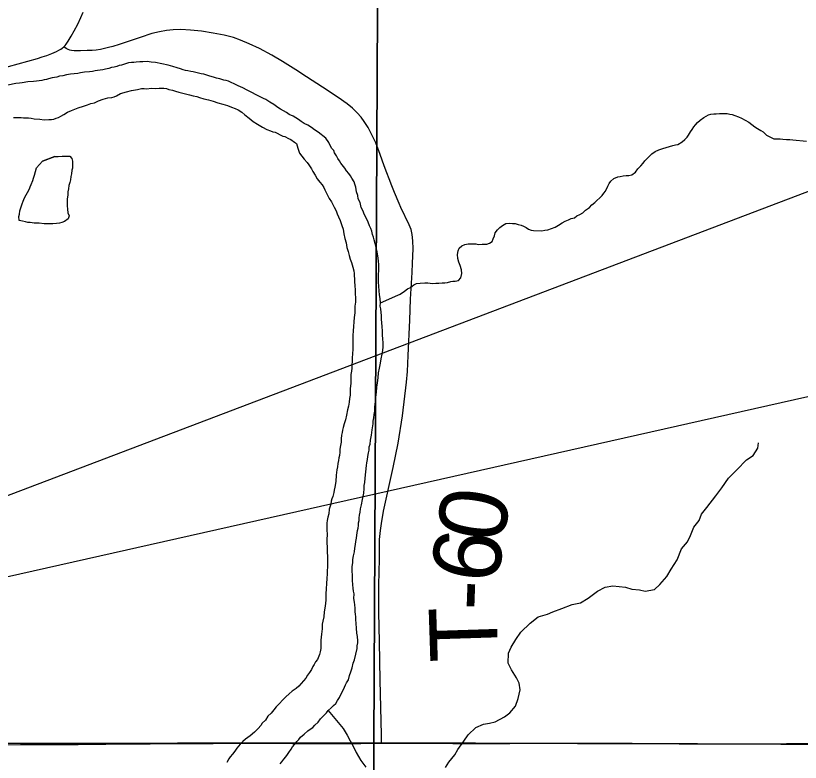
# Model space of a CAD drawing. Extents: x -17 to 88, y -5 to 22.
# Drawn here: x 6.404 to 7.061, y 17.134 to 17.759 of the extents above; entities that cross this region are included whole.
import ezdxf

# ---------------------------------------------------------------- set-up
doc = ezdxf.new("R2010")
doc.units = 0
for name, color, linetype in [('GM_X_County_Road', 7, 'Continuous'), ('GM_X_Major_River', 7, 'Continuous'), ('GM_X_Minor_Lake', 7, 'Continuous'), ('GM_X_Minor_River', 7, 'Continuous'), ('GM_X_Section', 7, 'Continuous'), ('GM_X_Township_Road', 7, 'Continuous'), ('GM_X_Township_Road_Text', 7, 'Continuous'), ('TX_P_10', 7, 'Continuous')]:
    doc.layers.add(name, color=color, linetype=linetype)

msp = doc.modelspace()

# ---------------------------------------------------------------- linework, layer by layer
at = {"layer": 'GM_X_County_Road'}
for points in [[(6.37699, 17.711), (6.38326, 17.71252), (6.39765, 17.71636), (6.42211, 17.72329), (6.4258, 17.72447), (6.42973, 17.72573), (6.4339, 17.72739), (6.43791, 17.72915), (6.43979, 17.73005), (6.4415, 17.73092), (6.44279, 17.73178), (6.44414, 17.73289)], [(5.97069, 17.14636), (6.02752, 17.14692), (6.1512, 17.14741), (6.20466, 17.14779), (6.24754, 17.14782), (6.31026, 17.14802), (6.39721, 17.14843), (6.40776, 17.14847), (6.42947, 17.14848), (6.45617, 17.14867), (6.50275, 17.14905), (6.51643, 17.1492), (6.56916, 17.14951), (6.60646, 17.14958), (6.63568, 17.14941), (6.69283, 17.14953), (6.70713, 17.14958), (6.71015, 17.14959)], [(6.71015, 17.14959), (6.76986, 17.14955), (6.81769, 17.14952), (6.85681, 17.14966), (6.89719, 17.14962), (6.92016, 17.14969), (6.97483, 17.14948), (7.01768, 17.14922), (7.04938, 17.14939), (7.11773, 17.14928), (7.13759, 17.14915), (7.21899, 17.14912)]]:
    msp.add_lwpolyline(points, dxfattribs=at)
at = {"layer": 'GM_X_Major_River'}
for points in [[(6.66717, 17.65023), (6.66608, 17.65291), (6.66348, 17.65638), (6.65711, 17.66143), (6.65411, 17.66339), (6.65148, 17.66534), (6.64848, 17.66729), (6.64547, 17.66887), (6.64283, 17.67043), (6.64058, 17.67199), (6.63833, 17.67355), (6.63607, 17.67474), (6.63268, 17.67632), (6.63043, 17.67788), (6.62817, 17.67944), (6.62553, 17.68063), (6.62328, 17.68219), (6.61991, 17.68453), (6.61652, 17.68649), (6.61314, 17.68883), (6.61126, 17.68963), (6.60862, 17.6912), (6.60523, 17.69278), (6.60147, 17.69474), (6.5977, 17.69671), (6.59394, 17.69868), (6.59017, 17.70027), (6.58677, 17.70185), (6.58413, 17.70304), (6.58187, 17.70422), (6.57998, 17.70464), (6.57809, 17.70505), (6.57469, 17.70626), (6.57203, 17.70669), (6.56939, 17.70749), (6.56636, 17.70831), (6.56372, 17.70912), (6.56145, 17.70992), (6.55918, 17.71034), (6.5569, 17.71076), (6.55464, 17.71157), (6.55236, 17.71199), (6.55047, 17.7124), (6.54782, 17.71283), (6.54592, 17.71325), (6.54403, 17.71366), (6.54177, 17.71446), (6.53912, 17.71527), (6.53534, 17.71648), (6.53156, 17.71769), (6.52096, 17.71979), (6.51716, 17.72024), (6.51375, 17.72068), (6.51032, 17.72036), (6.50766, 17.72042), (6.50461, 17.72009), (6.50271, 17.71975), (6.50081, 17.71978), (6.49814, 17.71945), (6.49584, 17.71874), (6.4924, 17.71766), (6.49049, 17.71732), (6.48858, 17.71659), (6.48628, 17.71588), (6.484, 17.71554), (6.4817, 17.71482), (6.47903, 17.71411), (6.47674, 17.71377), (6.47445, 17.71344), (6.47217, 17.7131), (6.47026, 17.71275), (6.46797, 17.71242), (6.46568, 17.71208), (6.4615, 17.71178), (6.45806, 17.71108), (6.45577, 17.71075), (6.45273, 17.71042), (6.44968, 17.7101), (6.44624, 17.7094), (6.44319, 17.7087), (6.44052, 17.70837), (6.43823, 17.70766), (6.43632, 17.70731), (6.43441, 17.70697), (6.43136, 17.70626), (6.42945, 17.70554), (6.42754, 17.7052), (6.42563, 17.70485), (6.42106, 17.70417), (6.41877, 17.70384), (6.41382, 17.70355), (6.40924, 17.70288), (6.40696, 17.70254), (6.40391, 17.70222), (6.39704, 17.70082)], [(6.40186, 17.67377), (6.40414, 17.67373), (6.40604, 17.6737), (6.40832, 17.67365), (6.41022, 17.67362), (6.41212, 17.67358), (6.4144, 17.67354), (6.41667, 17.67312), (6.41933, 17.67269), (6.42388, 17.67223), (6.42767, 17.67177), (6.43148, 17.67208), (6.43376, 17.67204), (6.43567, 17.67239), (6.43759, 17.67311), (6.4395, 17.67383), (6.44142, 17.67494), (6.44411, 17.67641), (6.44718, 17.67825), (6.45063, 17.6797), (6.456, 17.68188), (6.46059, 17.68331), (6.46403, 17.68439), (6.46671, 17.68548), (6.46976, 17.68618), (6.47321, 17.68764), (6.47704, 17.68908), (6.48086, 17.69015), (6.48429, 17.69047), (6.4862, 17.69119), (6.48812, 17.69192), (6.49158, 17.69375), (6.49654, 17.69518), (6.50074, 17.69624), (6.50571, 17.69729), (6.50914, 17.69798), (6.51142, 17.69794), (6.51332, 17.6979), (6.51751, 17.69821), (6.52055, 17.69815), (6.52398, 17.69847), (6.52778, 17.69839), (6.53005, 17.69797), (6.53194, 17.69718), (6.53497, 17.69674), (6.53762, 17.69593), (6.54026, 17.69512), (6.54934, 17.69268), (6.55237, 17.69186), (6.5554, 17.69142), (6.55767, 17.69062), (6.56145, 17.68942), (6.56523, 17.68858), (6.56901, 17.68737), (6.57317, 17.68616), (6.57733, 17.68494), (6.58111, 17.68373), (6.58451, 17.68253), (6.58753, 17.68133), (6.59017, 17.68014), (6.59317, 17.67819), (6.59579, 17.67586), (6.59916, 17.67314), (6.60253, 17.67042), (6.60629, 17.66807), (6.61043, 17.66572), (6.61419, 17.66375), (6.61721, 17.66256), (6.6191, 17.66176), (6.62099, 17.66134), (6.62288, 17.66055), (6.62514, 17.65937), (6.6274, 17.65819), (6.62929, 17.65777), (6.6323, 17.6562), (6.63419, 17.6554), (6.63719, 17.65307), (6.63907, 17.65189), (6.64014, 17.64808), (6.64158, 17.64387), (6.64529, 17.63887), (6.6479, 17.63616), (6.64938, 17.63424), (6.6516, 17.63078), (6.6527, 17.62848), (6.65454, 17.6254), (6.65638, 17.62233), (6.65861, 17.61963)], [(6.69093, 17.33422), (6.69134, 17.33611), (6.69139, 17.33839), (6.69181, 17.34066), (6.69224, 17.34331), (6.69267, 17.34596), (6.69349, 17.34936), (6.69434, 17.35391), (6.6952, 17.35921), (6.69565, 17.363), (6.6957, 17.36565), (6.69612, 17.36792), (6.69657, 17.37171), (6.69753, 17.38233), (6.69795, 17.3846), (6.69838, 17.38725), (6.69881, 17.3899), (6.69925, 17.39293), (6.69967, 17.3952), (6.69972, 17.39786), (6.70052, 17.40012), (6.70096, 17.40353), (6.7018, 17.40769), (6.70227, 17.41224), (6.70312, 17.41716), (6.70316, 17.41944), (6.70359, 17.42209), (6.70403, 17.42512), (6.70446, 17.42777), (6.70452, 17.43081), (6.70495, 17.43384), (6.7054, 17.43724), (6.70544, 17.43952), (6.7059, 17.44369), (6.70635, 17.44786), (6.70681, 17.45165), (6.70726, 17.45582), (6.70772, 17.45999), (6.70855, 17.46377), (6.70939, 17.46793), (6.70984, 17.47172), (6.71067, 17.4755), (6.71111, 17.47853), (6.71155, 17.48156), (6.71161, 17.48498), (6.71129, 17.4884), (6.71097, 17.49145), (6.71103, 17.49486), (6.71072, 17.49867), (6.7104, 17.50171), (6.71008, 17.50475), (6.71013, 17.50779), (6.7098, 17.51045), (6.70948, 17.5135), (6.70914, 17.51578), (6.70919, 17.51844), (6.70888, 17.52224), (6.70856, 17.52529), (6.70824, 17.52871), (6.70793, 17.53251), (6.70762, 17.53594), (6.70769, 17.53973), (6.70785, 17.54809), (6.70789, 17.55074), (6.70756, 17.55341), (6.70723, 17.55607), (6.70692, 17.55949), (6.70621, 17.56255), (6.70552, 17.56598), (6.7048, 17.56827), (6.7041, 17.57132), (6.70338, 17.57361), (6.70266, 17.5759), (6.70195, 17.57857), (6.70123, 17.58087), (6.70014, 17.58316), (6.69905, 17.58622), (6.69721, 17.58967), (6.69575, 17.59274), (6.69466, 17.59542), (6.6932, 17.59848), (6.69214, 17.60268), (6.69067, 17.60574), (6.69034, 17.60841), (6.68926, 17.61147), (6.68857, 17.61528), (6.68786, 17.61795), (6.68713, 17.61986), (6.68529, 17.62293), (6.68418, 17.62485), (6.6827, 17.62678), (6.68084, 17.62909), (6.67936, 17.6314), (6.67602, 17.63564), (6.67492, 17.63756), (6.67343, 17.63948), (6.67233, 17.64178), (6.67086, 17.64409), (6.67013, 17.646), (6.66865, 17.64793), (6.66717, 17.65023)], [(6.65861, 17.61963), (6.66047, 17.61732), (6.66195, 17.61501), (6.66267, 17.6131), (6.66634, 17.60582), (6.66819, 17.60313), (6.66929, 17.60083), (6.67039, 17.59853), (6.67223, 17.59545), (6.67295, 17.59316), (6.67404, 17.59049), (6.6755, 17.58742), (6.67694, 17.58322), (6.67803, 17.58016), (6.67837, 17.57825), (6.67872, 17.57635), (6.67941, 17.57254), (6.68048, 17.56872), (6.68117, 17.56491), (6.68224, 17.56147), (6.68294, 17.55804), (6.68402, 17.55498), (6.68511, 17.5523), (6.68618, 17.54849), (6.68688, 17.54544), (6.68722, 17.54315), (6.68719, 17.54125), (6.68752, 17.53859), (6.68748, 17.53631), (6.68779, 17.53289), (6.68811, 17.52946), (6.68804, 17.52567), (6.68837, 17.523), (6.6883, 17.51921), (6.68785, 17.5158), (6.6878, 17.51276), (6.68775, 17.5101), (6.68729, 17.50632), (6.68685, 17.50253), (6.68677, 17.49873), (6.68632, 17.49494), (6.68625, 17.49114), (6.68619, 17.48773), (6.68612, 17.48431), (6.68608, 17.48203), (6.68603, 17.47938), (6.68597, 17.47596), (6.68552, 17.47217), (6.68536, 17.46382), (6.68493, 17.46117), (6.6845, 17.45852), (6.68443, 17.45434), (6.68436, 17.45093), (6.6839, 17.44676), (6.68384, 17.44334), (6.6838, 17.44106), (6.68337, 17.43842), (6.68293, 17.43538), (6.68249, 17.43197), (6.68167, 17.42895), (6.68083, 17.42441), (6.67999, 17.42063), (6.67879, 17.41723), (6.67797, 17.41421), (6.67755, 17.41194), (6.67714, 17.41005), (6.67671, 17.40778), (6.67628, 17.40475), (6.67622, 17.40171), (6.67579, 17.39906), (6.67535, 17.39603), (6.6753, 17.39338), (6.67488, 17.39072), (6.67446, 17.38883), (6.67404, 17.38656), (6.67361, 17.38391), (6.67318, 17.38126), (6.67275, 17.37861), (6.67228, 17.37406), (6.6718, 17.36876), (6.67096, 17.36421), (6.67053, 17.36156), (6.67011, 17.35967), (6.66929, 17.35627), (6.66849, 17.35439), (6.66808, 17.3525), (6.66765, 17.34985), (6.66643, 17.34569), (6.66598, 17.3419), (6.66516, 17.33888), (6.66474, 17.33623), (6.66431, 17.33396), (6.66426, 17.3313), (6.66421, 17.32827), (6.66451, 17.32446), (6.66444, 17.32029), (6.66465, 17.31117), (6.66491, 17.30471), (6.66486, 17.30243), (6.66482, 17.29977), (6.66477, 17.29749)], [(6.62519, 17.13228), (6.62675, 17.13415), (6.62831, 17.1364), (6.62987, 17.13827), (6.63142, 17.14014), (6.6326, 17.14202), (6.63455, 17.14464), (6.63572, 17.14652), (6.63767, 17.14876), (6.63923, 17.15101), (6.64078, 17.15288), (6.64234, 17.15475), (6.64543, 17.15735), (6.64852, 17.15995), (6.65045, 17.16143), (6.65276, 17.16291), (6.65431, 17.16478), (6.65702, 17.16739), (6.65897, 17.17001), (6.66168, 17.17262), (6.66401, 17.17523), (6.66557, 17.1771), (6.66789, 17.17934), (6.66983, 17.1812), (6.67176, 17.18306), (6.67332, 17.18531), (6.67489, 17.18794), (6.67647, 17.19095), (6.67805, 17.19396), (6.67924, 17.19659), (6.68003, 17.19848), (6.68083, 17.20036), (6.68239, 17.20261), (6.68322, 17.20639), (6.68442, 17.20941), (6.68562, 17.2128), (6.68645, 17.21659), (6.68765, 17.2196), (6.68973, 17.22906), (6.68977, 17.23133), (6.69019, 17.2336), (6.69023, 17.2355), (6.68991, 17.23893), (6.68959, 17.24197), (6.68929, 17.24615), (6.68898, 17.24996), (6.68866, 17.25338), (6.6887, 17.25566), (6.68836, 17.25756), (6.68802, 17.25985), (6.68808, 17.26288), (6.68775, 17.26555), (6.68741, 17.26783), (6.68709, 17.27088), (6.68716, 17.27467), (6.68682, 17.27696), (6.68649, 17.27962), (6.68616, 17.28229), (6.68585, 17.28609), (6.68593, 17.29027), (6.68562, 17.29407), (6.68568, 17.29749), (6.68613, 17.3009), (6.68617, 17.30355), (6.68661, 17.30658), (6.68743, 17.30998), (6.68787, 17.31301), (6.68831, 17.31605), (6.68874, 17.3187), (6.68917, 17.32134), (6.6896, 17.32399), (6.69005, 17.32778), (6.69046, 17.32967), (6.69089, 17.33195), (6.69093, 17.33422)], [(6.66477, 17.29749), (6.66471, 17.29408), (6.66466, 17.29142), (6.66421, 17.28763), (6.66413, 17.28346), (6.66367, 17.27891), (6.66359, 17.27473), (6.66349, 17.26942), (6.66302, 17.26449), (6.66216, 17.25957), (6.66171, 17.2554), (6.66088, 17.252), (6.66045, 17.24935), (6.66038, 17.24555), (6.65992, 17.241), (6.65944, 17.23607), (6.65941, 17.23418), (6.65936, 17.23152), (6.65931, 17.22886), (6.65888, 17.22621), (6.65808, 17.22395), (6.65648, 17.2198), (6.65492, 17.21793), (6.65374, 17.21567), (6.65257, 17.2138), (6.65138, 17.21154), (6.64981, 17.20891), (6.64825, 17.20666), (6.64668, 17.20403), (6.64474, 17.20179), (6.64279, 17.19955), (6.64085, 17.19731), (6.63854, 17.19545), (6.63545, 17.19323), (6.63275, 17.191), (6.63004, 17.1884), (6.6219, 17.18019), (6.61996, 17.17757), (6.61763, 17.17495), (6.61492, 17.17235), (6.61295, 17.16897), (6.61024, 17.16636), (6.60907, 17.16448), (6.60674, 17.16187), (6.60364, 17.15888), (6.60016, 17.15591), (6.5963, 17.15295), (6.59399, 17.15109), (6.59167, 17.14885), (6.58894, 17.14549), (6.58737, 17.14286), (6.58543, 17.14062), (6.58349, 17.13837), (6.58231, 17.1365), (6.58073, 17.13349)]]:
    msp.add_lwpolyline(points, dxfattribs=at)
at = {"layer": 'GM_X_Minor_Lake'}
msp.add_lwpolyline([(6.42627, 17.63724), (6.43661, 17.64123), (6.42627, 17.63724), (6.43661, 17.64123), (6.43927, 17.64118), (6.4427, 17.6415), (6.4446, 17.64146), (6.4465, 17.64143), (6.44916, 17.64138), (6.45064, 17.63945), (6.45136, 17.63716), (6.45132, 17.63488), (6.45125, 17.63146), (6.45084, 17.62957), (6.4504, 17.62654), (6.44998, 17.62427), (6.44955, 17.62162), (6.44913, 17.61935), (6.44832, 17.61671), (6.44789, 17.61406), (6.44746, 17.61141), (6.44741, 17.60875), (6.44697, 17.60572), (6.44692, 17.60268), (6.44686, 17.59965), (6.44719, 17.59698), (6.44751, 17.59394), (6.4486, 17.59126), (6.4478, 17.589), (6.44472, 17.58677), (6.44242, 17.58568), (6.44051, 17.58533), (6.43784, 17.585), (6.43479, 17.58468), (6.43099, 17.58475), (6.42757, 17.58481), (6.4234, 17.58527), (6.41922, 17.58535), (6.41581, 17.58579), (6.4139, 17.58583), (6.41201, 17.58624), (6.40937, 17.58705), (6.40671, 17.58748), (6.4064, 17.59091), (6.40681, 17.5928), (6.40724, 17.59545), (6.40845, 17.59884), (6.40925, 17.60149), (6.41006, 17.60375), (6.41125, 17.60638), (6.41244, 17.60902), (6.41361, 17.6109), (6.41519, 17.61391), (6.41599, 17.61579), (6.41678, 17.61767), (6.41799, 17.62107), (6.41878, 17.62295), (6.41959, 17.6256), (6.42041, 17.62862), (6.42122, 17.63164), (6.42627, 17.63724)], dxfattribs=at)
at = {"layer": 'GM_X_Minor_River'}
for points in [[(6.9458, 17.64771), (6.95421, 17.65021), (6.9565, 17.65093), (6.95841, 17.65127), (6.96187, 17.65349), (6.96419, 17.65534), (6.96613, 17.6572), (6.9673, 17.65908), (6.96887, 17.66171), (6.97043, 17.66358), (6.97161, 17.66584), (6.97317, 17.66771), (6.97472, 17.66958), (6.97704, 17.67143), (6.98012, 17.67365), (6.98396, 17.67586), (6.98588, 17.67659), (6.98854, 17.67691), (6.99044, 17.67688), (6.99311, 17.67721), (6.99501, 17.67717), (6.99729, 17.67713), (6.99957, 17.67709), (7.00185, 17.67667), (7.00374, 17.67625), (7.006, 17.67545), (7.00903, 17.67426), (7.01166, 17.67307), (7.01467, 17.67149), (7.01769, 17.66992), (7.02031, 17.66797), (7.02294, 17.66602), (7.02519, 17.66446), (7.02782, 17.66289), (7.0297, 17.66172), (7.03269, 17.65901), (7.03532, 17.65744), (7.03872, 17.65585), (7.041, 17.65581), (7.04404, 17.65576), (7.04632, 17.65571), (7.04935, 17.65528), (7.05201, 17.65523), (7.05467, 17.65518), (7.06605, 17.65383)], [(6.70919, 17.51844), (6.72376, 17.525), (6.72567, 17.52573), (6.72953, 17.52831), (6.73184, 17.53017), (6.73452, 17.53126), (6.73723, 17.53349), (6.73953, 17.53458), (6.74257, 17.53491), (6.74638, 17.53522), (6.74904, 17.53517), (6.75284, 17.53472), (6.7555, 17.53505), (6.75816, 17.535), (6.76083, 17.53533), (6.76311, 17.53528), (6.7654, 17.53562), (6.76807, 17.53633), (6.76998, 17.53668), (6.77188, 17.53664), (6.77456, 17.53735), (6.7765, 17.53959), (6.77732, 17.54299), (6.777, 17.54604), (6.77593, 17.54986), (6.77484, 17.55253), (6.77414, 17.55559), (6.77382, 17.55901), (6.77426, 17.56204), (6.77506, 17.5643), (6.77737, 17.56616), (6.78006, 17.56725), (6.78273, 17.56796), (6.78577, 17.5679), (6.78919, 17.56784), (6.79109, 17.56742), (6.79451, 17.56774), (6.79831, 17.56767), (6.80061, 17.56838), (6.80292, 17.56986), (6.80372, 17.57213), (6.80491, 17.57476), (6.80533, 17.57703), (6.80728, 17.57965), (6.80922, 17.58152), (6.81153, 17.58337), (6.81422, 17.58484), (6.81765, 17.58516), (6.81993, 17.58511), (6.82221, 17.58507), (6.82448, 17.58427), (6.82712, 17.58346), (6.82901, 17.58267), (6.83127, 17.58149), (6.83315, 17.58031), (6.83541, 17.57951), (6.83731, 17.57909), (6.84453, 17.57896), (6.84682, 17.5793), (6.84948, 17.57963), (6.85254, 17.58071), (6.8556, 17.58179), (6.8583, 17.58364), (6.86138, 17.58548), (6.86407, 17.58695), (6.86675, 17.58804), (6.86905, 17.58914), (6.87172, 17.58985), (6.87365, 17.59133), (6.87633, 17.59242), (6.87864, 17.5939), (6.88096, 17.59613), (6.88443, 17.59834), (6.88637, 17.60059), (6.88869, 17.60244), (6.89062, 17.60431), (6.89294, 17.60654), (6.89488, 17.6084), (6.89644, 17.61027), (6.89761, 17.61215), (6.89959, 17.61629), (6.90077, 17.61855), (6.90233, 17.62042), (6.90465, 17.62265), (6.9081, 17.62411), (6.91001, 17.62445), (6.91267, 17.62478), (6.91496, 17.62512), (6.91724, 17.62508), (6.91992, 17.62578), (6.923, 17.62801), (6.92495, 17.63063), (6.92728, 17.63324), (6.92922, 17.63549), (6.93078, 17.63736), (6.93233, 17.63923), (6.93427, 17.64109), (6.93659, 17.64332), (6.93929, 17.64517), (6.94236, 17.64663), (6.9458, 17.64771)], [(6.76379, 17.12927), (6.76648, 17.1338), (6.77146, 17.13982), (6.77416, 17.14434), (6.77914, 17.1515), (6.7826, 17.15678), (6.7891, 17.16278), (6.79557, 17.16575), (6.8005, 17.16646), (6.80544, 17.16755), (6.81306, 17.17164), (6.81764, 17.17501), (6.82223, 17.18066), (6.82456, 17.18708), (6.82614, 17.19427), (6.82543, 17.19997), (6.82319, 17.20454), (6.81907, 17.21103), (6.81609, 17.21675), (6.81654, 17.22509), (6.81885, 17.23), (6.8227, 17.23641), (6.82692, 17.24281), (6.83457, 17.25032), (6.84144, 17.25557), (6.84904, 17.25777), (6.8536, 17.25962), (6.86121, 17.26258), (6.86996, 17.2659), (6.8768, 17.26735), (6.88327, 17.27108), (6.89091, 17.27707), (6.89738, 17.28042), (6.90383, 17.28149), (6.90914, 17.28106), (6.91444, 17.28025), (6.91974, 17.27868), (6.92618, 17.27824), (6.9311, 17.27705), (6.93869, 17.27849), (6.94328, 17.28262), (6.94902, 17.28939), (6.95286, 17.29542), (6.95786, 17.30333), (6.96135, 17.3124), (6.96632, 17.31842), (6.96903, 17.3237), (6.97174, 17.3305), (6.97633, 17.33615), (6.97827, 17.34144), (6.98249, 17.34709), (6.99015, 17.35687), (6.99514, 17.36365), (7.00089, 17.37156), (7.00778, 17.3787), (7.01581, 17.38696), (7.02153, 17.3907), (7.02537, 17.39673), (7.02579, 17.40127)], [(6.66557, 17.1771), (6.678, 17.162), (6.68136, 17.15627), (6.68398, 17.1517), (6.68659, 17.14674), (6.68882, 17.14178), (6.69294, 17.1353), (6.69706, 17.12956)]]:
    msp.add_lwpolyline(points, dxfattribs=at)
at = {"layer": 'GM_X_Section'}
for points in [[(5.72325, 18.14993), (6.70875, 18.15498), (6.70378, 17.14986), (5.71596, 17.14827)], [(6.70875, 18.15498), (7.72901, 18.14763), (7.72672, 17.14664), (6.70378, 17.14986)], [(5.71596, 17.14827), (6.70378, 17.14986), (6.70945, 16.1492), (5.71414, 16.14656)], [(6.70378, 17.14986), (7.72672, 17.14664), (7.71159, 16.15106), (6.70945, 16.1492)]]:
    msp.add_lwpolyline(points, close=True, dxfattribs=at)
at = {"layer": 'GM_X_Township_Road'}
for points in [[(6.44414, 17.73289), (6.44509, 17.73395), (6.44598, 17.73512), (6.44774, 17.73777), (6.45031, 17.74198), (6.45281, 17.74637), (6.45579, 17.75181), (6.4584, 17.75744), (6.46014, 17.76208)], [(6.71015, 17.14959), (6.71, 17.15667), (6.70898, 17.20238), (6.70851, 17.2347), (6.70796, 17.25954), (6.70791, 17.2676), (6.70802, 17.28245), (6.70811, 17.29298), (6.70839, 17.30413), (6.70841, 17.3139), (6.70856, 17.32022), (6.70933, 17.32777), (6.7101, 17.33361), (6.71194, 17.34393), (6.71994, 17.38059), (6.7241, 17.40107), (6.72775, 17.42391), (6.73101, 17.45205), (6.73178, 17.46098), (6.73239, 17.47453), (6.73376, 17.5041), (6.73453, 17.5215), (6.7353, 17.53505), (6.73576, 17.54383), (6.73606, 17.55168), (6.73652, 17.5637), (6.73636, 17.57047), (6.73575, 17.57571), (6.73503, 17.57984), (6.73341, 17.58385), (6.72646, 17.59835), (6.72493, 17.60172), (6.72112, 17.61082), (6.71883, 17.61657), (6.71655, 17.62234), (6.71453, 17.62755), (6.71234, 17.63336), (6.70894, 17.64269), (6.70529, 17.65257), (6.70245, 17.65876), (6.69892, 17.6653), (6.69564, 17.67054), (6.69305, 17.67402), (6.68976, 17.67773), (6.68571, 17.68159), (6.68138, 17.68513), (6.67375, 17.69047), (6.66083, 17.69911), (6.64728, 17.70791), (6.63839, 17.71362), (6.63157, 17.71795), (6.62734, 17.72056), (6.61824, 17.72592), (6.60783, 17.73149), (6.59939, 17.73546), (6.59195, 17.73859), (6.58609, 17.74065), (6.57827, 17.74268), (6.56913, 17.74453), (6.5593, 17.74603), (6.55003, 17.74697), (6.54197, 17.74738), (6.53576, 17.74725), (6.53019, 17.74671), (6.52407, 17.74565), (6.51781, 17.74403), (6.50811, 17.74091), (6.49038, 17.73481), (6.48502, 17.73325), (6.48142, 17.73232), (6.4782, 17.73147), (6.47479, 17.73076), (6.47111, 17.73023), (6.46789, 17.72998), (6.46355, 17.72977), (6.45808, 17.72954), (6.45479, 17.72961), (6.45269, 17.72966), (6.45059, 17.7299), (6.44916, 17.73018), (6.44765, 17.73059), (6.44608, 17.73149), (6.44414, 17.73289)]]:
    msp.add_lwpolyline(points, dxfattribs=at)
at = {"layer": 'TX_P_10'}
msp.add_lwpolyline([(5.95665, 17.18984), (9.68242, 18.60587), (9.68242, 18.02859)], close=True, dxfattribs=at)

# ---------------------------------------------------------------- texts
at = {"layer": 'GM_X_Township_Road_Text'}
for s, rotation, p in [('0', 81.202, (6.81202, 17.31639)), ('6', 82.05425, (6.80721, 17.28195)), ('-', 87.90749, (6.80649, 17.26016)), ('T', 91.84741, (6.80787, 17.21872))]:
    msp.add_text(s, height=0.05682, rotation=rotation, dxfattribs=at).set_placement(p)

doc.saveas('drawing.dxf')
